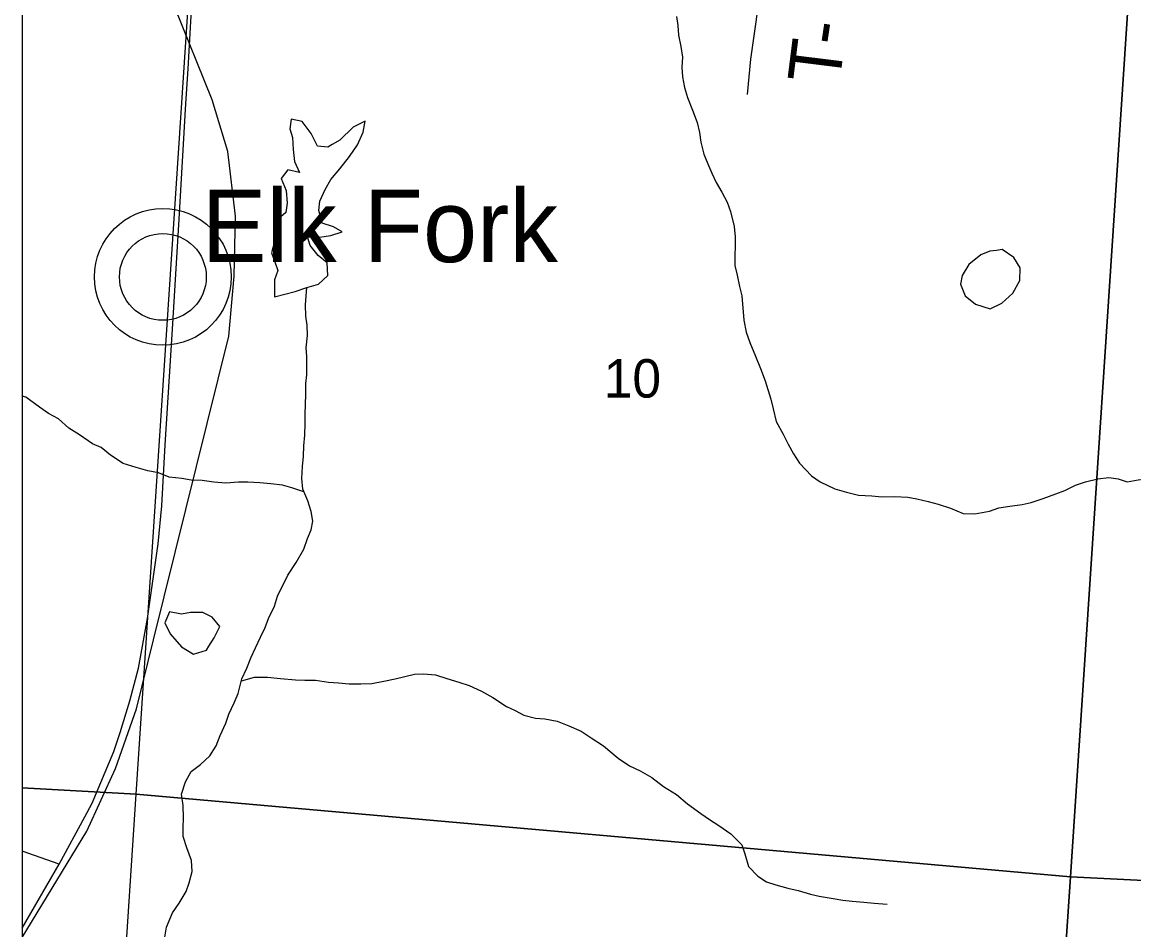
# Model space of a CAD drawing. Extents: x 0 to 34, y 0 to 22.
# Drawn here: x 2.1 to 3.309, y 16.998 to 17.985 of the extents above; entities that cross this region are included whole.
import ezdxf

# ---------------------------------------------------------------- set-up
doc = ezdxf.new("R2010")
doc.units = 0
for name, color, linetype in [('Default', 7, 'Continuous'), ('GM_X_County_Road', 7, 'Continuous'), ('GM_X_Minor_Lake', 7, 'Continuous'), ('GM_X_Minor_River', 7, 'Continuous'), ('GM_X_Rail_Line', 7, 'Continuous'), ('GM_X_Section', 7, 'Continuous'), ('GM_X_Section_Text', 7, 'Continuous'), ('GM_X_State_Route', 7, 'Continuous'), ('GM_X_Township_Road', 7, 'Continuous'), ('GM_X_Township_Road_Text', 7, 'Continuous'), ('GM_X_Unincorporated', 7, 'Continuous'), ('GM_X_Unincorporated_Location', 7, 'Continuous'), ('GM_X_Unincorporated_Text', 7, 'Continuous'), ('SC_Scratch1', 7, 'Continuous'), ('SH_Data', 7, 'Continuous')]:
    doc.layers.add(name, color=color, linetype=linetype)

msp = doc.modelspace()

# ---------------------------------------------------------------- linework, layer by layer
at = {"layer": 'Default'}
for points in [[(2.1, 18.1694), (2.1, 17.1522), (2.2239, 17.1453), (2.2906, 18.1558)], [(2.1, 17.1522), (2.1, 16.1183), (2.1564, 16.1145), (2.2239, 17.1453)]]:
    msp.add_lwpolyline(points, close=True, dxfattribs=at)
at = {"layer": 'GM_X_County_Road'}
msp.add_line((2.14, 17.0693), (2.1, 17.0835), dxfattribs=at)
at = {"layer": 'GM_X_Minor_Lake'}
for points in [[(2.4371, 17.8521), (2.4323, 17.8492), (2.421, 17.8504), (2.4141, 17.864), (2.4042, 17.8769), (2.3925, 17.8795), (2.391, 17.8692), (2.3937, 17.8598), (2.3945, 17.8465), (2.396, 17.8336), (2.4014, 17.8215), (2.3889, 17.8245), (2.3817, 17.815), (2.387, 17.8021), (2.3882, 17.7881), (2.3867, 17.7782), (2.3762, 17.7691), (2.3758, 17.7562), (2.3744, 17.7467), (2.371, 17.7342), (2.3748, 17.7244), (2.3779, 17.7149), (2.3741, 17.705), (2.3742, 17.6865)], [(2.3742, 17.6865), (2.3969, 17.6922), (2.4093, 17.6964), (2.4222, 17.7002), (2.4324, 17.7097), (2.4316, 17.7234), (2.4217, 17.7313), (2.413, 17.7423), (2.4103, 17.7517), (2.4232, 17.7514), (2.4357, 17.7529), (2.4478, 17.7571), (2.4383, 17.7624), (2.4261, 17.7666), (2.4223, 17.7802), (2.4234, 17.7905), (2.4294, 17.803), (2.4355, 17.814), (2.4453, 17.8254), (2.4558, 17.8391), (2.4645, 17.8516), (2.4705, 17.8653), (2.4727, 17.8774), (2.4599, 17.8709), (2.4452, 17.8569), (2.4371, 17.8521)], [(3.1593, 17.7369), (3.1519, 17.7361), (3.1421, 17.7319), (3.1292, 17.7216), (3.1221, 17.7095), (3.1202, 17.7), (3.1252, 17.6875), (3.1366, 17.6784), (3.1525, 17.6732)], [(3.1525, 17.6732), (3.165, 17.6796), (3.177, 17.6903), (3.1846, 17.704), (3.1849, 17.718), (3.178, 17.7293), (3.1655, 17.7377), (3.1593, 17.7369)], [(2.2602, 17.3437), (2.2549, 17.3316), (2.2607, 17.3199), (2.2732, 17.3055), (2.2861, 17.2975), (2.3005, 17.3021), (2.303, 17.3063)], [(2.303, 17.3063), (2.3087, 17.3154), (2.3148, 17.3276), (2.3064, 17.3378), (2.2962, 17.3431), (2.2829, 17.343), (2.2731, 17.3411), (2.2602, 17.3437)]]:
    msp.add_lwpolyline(points, dxfattribs=at)
at = {"layer": 'GM_X_Minor_River'}
for points in [[(2.8115, 17.9912), (2.8127, 17.9814), (2.8135, 17.9708), (2.8162, 17.9586), (2.8177, 17.9469), (2.817, 17.9363), (2.8178, 17.9256), (2.8201, 17.9139), (2.8232, 17.9033), (2.8289, 17.8893), (2.8339, 17.876), (2.8362, 17.865), (2.8377, 17.8544), (2.8412, 17.8415), (2.8454, 17.8309), (2.8499, 17.8207), (2.8545, 17.8108), (2.8606, 17.8002), (2.8663, 17.7893), (2.8701, 17.779), (2.874, 17.7627), (2.8751, 17.7517), (2.8752, 17.7415), (2.8748, 17.7313), (2.8749, 17.7203), (2.8772, 17.71), (2.8799, 17.6975), (2.8822, 17.6873), (2.8845, 17.6608), (2.8872, 17.6479), (2.891, 17.6365), (2.8971, 17.6217), (2.9025, 17.6085), (2.9078, 17.5948), (2.9139, 17.5751), (2.9166, 17.5645), (2.9197, 17.5509), (2.9273, 17.5369), (2.9327, 17.5259), (2.9384, 17.5157), (2.9452, 17.5054), (2.9581, 17.4918), (2.9676, 17.485), (2.9835, 17.4775), (2.996, 17.4737), (3.0093, 17.4707), (3.0237, 17.47), (3.0347, 17.4689), (3.0487, 17.4693), (3.0627, 17.4686), (3.0725, 17.4667), (3.085, 17.4637), (3.096, 17.4607), (3.1093, 17.4565), (3.1229, 17.4505), (3.1358, 17.4502), (3.1517, 17.4532), (3.1619, 17.4567), (3.1736, 17.4586)], [(2.4096, 17.6213), (2.4088, 17.6308), (2.4103, 17.6441), (2.4098, 17.6554), (2.4083, 17.6653), (2.4079, 17.6778), (2.4093, 17.6964)], [(2.2549, 16.9899), (2.2568, 17.0006), (2.2635, 17.0161), (2.2707, 17.0268), (2.2782, 17.0393), (2.2816, 17.0488), (2.2846, 17.0613), (2.2842, 17.0731), (2.2788, 17.0871), (2.275, 17.0992), (2.275, 17.1087), (2.2753, 17.1197), (2.2749, 17.1329), (2.2733, 17.1455), (2.2775, 17.1587), (2.2835, 17.1701), (2.2937, 17.1777), (2.3039, 17.1872), (2.311, 17.1979), (2.3151, 17.2093), (2.3212, 17.2225), (2.3245, 17.2324), (2.3306, 17.2446), (2.3347, 17.2548), (2.3388, 17.2707), (2.3441, 17.2825), (2.3489, 17.2943), (2.3538, 17.3045), (2.3591, 17.3163), (2.364, 17.3266), (2.3677, 17.3364), (2.3741, 17.3497), (2.3775, 17.3607), (2.3888, 17.3835), (2.3978, 17.3975), (2.4061, 17.412), (2.4102, 17.4234), (2.414, 17.4329), (2.4158, 17.4423), (2.4143, 17.4529), (2.4105, 17.4643), (2.4051, 17.4772), (2.404, 17.4886), (2.4047, 17.5018), (2.4058, 17.5132), (2.4061, 17.5242), (2.4072, 17.536), (2.4075, 17.5485), (2.4075, 17.5591), (2.4079, 17.569), (2.4082, 17.5807), (2.4085, 17.5921), (2.4093, 17.6016), (2.4096, 17.6118), (2.4096, 17.6213)], [(2.4063, 17.4744), (2.393, 17.4787), (2.3828, 17.4813), (2.3703, 17.4828), (2.3585, 17.4839), (2.3453, 17.4846), (2.3351, 17.4846), (2.3214, 17.4838), (2.3082, 17.4849), (2.2957, 17.4864), (2.2836, 17.4868), (2.2734, 17.4886), (2.2597, 17.4901), (2.248, 17.495), (2.2366, 17.4969), (2.2237, 17.5006), (2.2097, 17.5052), (2.1961, 17.5142), (2.1858, 17.5225), (2.1763, 17.5263), (2.1623, 17.5361), (2.1505, 17.5433), (2.1395, 17.5535), (2.1285, 17.5596), (2.1187, 17.5664), (2.1039, 17.5773), (2.1, 17.5783)], [(3.1736, 17.4586), (3.1873, 17.4605), (3.1971, 17.4628), (3.2099, 17.467), (3.2236, 17.472), (3.2334, 17.4758), (3.2451, 17.4815), (3.2561, 17.485), (3.2693, 17.4884), (3.2814, 17.4899), (3.2916, 17.4885), (3.3015, 17.4851), (3.3132, 17.4874), (3.3242, 17.4889), (3.3348, 17.4795)], [(2.3383, 17.2686), (2.3524, 17.2727), (2.3668, 17.2727), (2.3808, 17.2712), (2.3971, 17.2698), (2.4073, 17.2694), (2.4187, 17.2694), (2.4331, 17.2672), (2.4437, 17.2665), (2.4554, 17.2653), (2.4683, 17.2654), (2.48, 17.2658), (2.4933, 17.2681), (2.5054, 17.2708), (2.5159, 17.2735), (2.5265, 17.2758), (2.5364, 17.2762), (2.5493, 17.2751), (2.5618, 17.2713), (2.5746, 17.2672), (2.586, 17.2634), (2.5993, 17.2574), (2.6118, 17.2506), (2.6266, 17.2407), (2.6361, 17.2362), (2.6455, 17.2313), (2.658, 17.2279), (2.6683, 17.2272), (2.6815, 17.2246), (2.6944, 17.2197), (2.7077, 17.214), (2.7187, 17.2068), (2.732, 17.1978), (2.7479, 17.1845), (2.7604, 17.1762), (2.7718, 17.1706), (2.7847, 17.1634), (2.7972, 17.1536), (2.8112, 17.1449), (2.8234, 17.135), (2.8378, 17.1245), (2.8473, 17.1177), (2.8572, 17.1112), (2.8704, 17.1022), (2.8822, 17.0901), (2.8856, 17.0806), (2.8895, 17.0666), (2.8997, 17.056), (2.9092, 17.0499), (2.9194, 17.0469), (2.9323, 17.0432), (2.9437, 17.0405), (2.957, 17.0364), (2.9664, 17.0345), (2.9816, 17.0319), (2.9922, 17.03), (3.0024, 17.0289), (3.0149, 17.0278), (3.0263, 17.0267), (3.0403, 17.0256)]]:
    msp.add_lwpolyline(points, dxfattribs=at)
at = {"layer": 'GM_X_Rail_Line'}
msp.add_lwpolyline([(2.1, 16.9893), (2.1704, 17.1051), (2.2013, 17.1731), (2.2243, 17.2382), (2.2428, 17.3133), (2.3248, 17.6437), (2.3306, 17.7087), (2.3319, 17.774), (2.3234, 17.8446), (2.3066, 17.9007), (2.2655, 18.002), (2.1, 18.4495)], dxfattribs=at)
at = {"layer": 'GM_X_Section'}
for points in [[(2.2906, 18.1558), (3.3075, 18.0826), (3.2396, 17.0555), (2.2239, 17.1453)], [(4.3187, 18.0057), (4.2561, 17.0047), (3.2396, 17.0555), (3.3075, 18.0826)], [(3.2396, 17.0555), (3.1721, 16.0496), (2.1564, 16.1145), (2.2239, 17.1453)], [(3.2396, 17.0555), (4.2561, 17.0047), (4.189, 15.9719), (3.1721, 16.0496)]]:
    msp.add_lwpolyline(points, close=True, dxfattribs=at)
at = {"layer": 'GM_X_State_Route'}
for points in [[(2.168, 17.1208), (2.176, 17.1355), (2.1997, 17.1916), (2.2065, 17.2125), (2.217, 17.2467), (2.2264, 17.2823), (2.2362, 17.3366), (2.2477, 17.4176), (2.2517, 17.4591), (2.2555, 17.5254), (2.2633, 17.6513), (2.2706, 17.7708), (2.2779, 17.8962), (2.2804, 17.9343), (2.2859, 18.031), (2.2941, 18.1548)], [(2.1, 16.9997), (2.14, 17.0693), (2.168, 17.1208)]]:
    msp.add_lwpolyline(points, dxfattribs=at)
at = {"layer": 'GM_X_Township_Road'}
msp.add_lwpolyline([(2.8886, 17.9063), (2.8922, 17.9448), (2.8977, 17.9828), (2.9042, 18.0306), (2.9097, 18.0671), (2.9136, 18.0887), (2.9161, 18.1067), (2.915, 18.115), (2.9125, 18.1254)], dxfattribs=at)
at = {"layer": 'GM_X_Unincorporated'}
for radius in [0.0744, 0.0472]:
    msp.add_circle((2.2529, 17.708), radius, dxfattribs=at)
at = {"layer": 'GM_X_Unincorporated_Location'}
msp.add_line((2.2529, 17.708), (2.2529, 17.708), dxfattribs=at)
at = {"layer": 'SC_Scratch1'}
msp.add_lwpolyline([(2.1, 19.1982), (2.1, 14.1), (5.0535, 14.1), (5.0814, 14.5016), (5.1049, 14.8414), (5.1794, 15.9156), (5.2761, 17.2534), (5.2869, 17.4026), (5.3506, 18.2846), (5.3662, 18.4999), (5.4007, 18.9779), (5.182, 18.9932), (4.7997, 19.0196), (4.7394, 19.0241), (4.3628, 19.0495), (3.3448, 19.1146), (2.3572, 19.1804)], close=True, dxfattribs=at)
at = {"layer": 'SH_Data'}
msp.add_line((2.1, 20.9), (2.1, 14.1), dxfattribs=at)

# ---------------------------------------------------------------- texts
at = {"layer": 'GM_X_Section_Text'}
msp.add_text('10', height=0.04186, rotation=0, dxfattribs=at).set_placement((2.7323, 17.5767))
at = {"layer": 'GM_X_Township_Road_Text'}
for s, rotation, p in [('-', 81.5862, (2.9936, 17.958)), ('T', 82.9281, (2.9884, 17.9161))]:
    msp.add_text(s, height=0.0568, rotation=rotation, dxfattribs=at).set_placement(p)
at = {"layer": 'GM_X_Unincorporated_Text'}
msp.add_text('Elk Fork', height=0.07898, rotation=0, dxfattribs=at).set_placement((2.2952, 17.7241))

doc.saveas('drawing.dxf')
